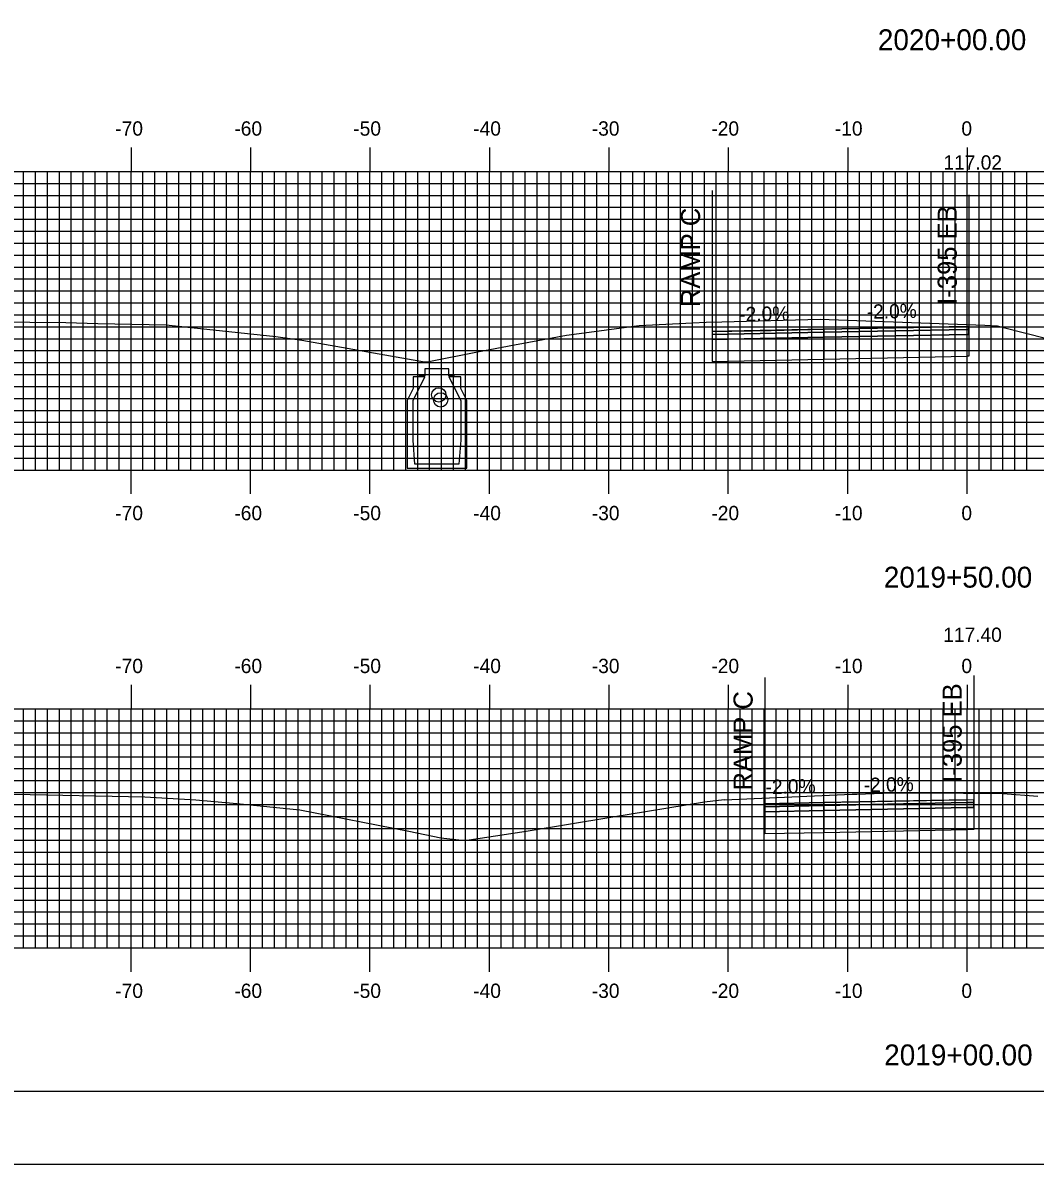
# Model space of a CAD drawing. Extents: x 855468 to 855811, y 366605 to 366825.
# Drawn here: x 855554.5 to 855639.3, y 366604.9 to 366700.5 of the extents above; entities that cross this region are included whole.
import ezdxf

# ---------------------------------------------------------------- set-up
doc = ezdxf.new("R2010")
doc.units = 0
for name, color, linetype in [('ANNOTATION', 7, 'Continuous'), ('BORDER', 7, 'Continuous'), ('D_Roadway_Centerline', 7, 'Continuous'), ('D_Roadway_Centerline_Text', 7, 'Continuous'), ('D_Roadway_Edge_Shoulder', 7, 'Continuous'), ('D_Roadway_Edge_TW', 7, 'Continuous'), ('D_Roadway_Pavement', 7, 'Continuous'), ('D_Roadway_SubGrade', 7, 'Continuous'), ('H_V ANNOTATION', 7, 'Continuous'), ('M_Roadway_Centerline', 7, 'Continuous'), ('MAJOR', 7, 'Continuous'), ('MINOR', 7, 'Continuous'), ('PLOT BOUNDARY', 7, 'Continuous'), ('S_Drainage_CB', 7, 'Continuous'), ('S_Drainage_Invert', 7, 'Continuous'), ('S_Roadway_Centerline', 7, 'Continuous')]:
    doc.layers.add(name, color=color, linetype=linetype)

msp = doc.modelspace()

# ---------------------------------------------------------------- linework, layer by layer
at = {"layer": 'BORDER'}
msp.add_lwpolyline([(855483.982, 366611.055), (855803.982, 366611.055), (855803.982, 366821.055), (855483.982, 366821.055)], close=True, dxfattribs=at)
at = {"layer": 'D_Roadway_Centerline'}
for points in [[(855612.235, 366674.653), (855612.237, 366674.653), (855617.18, 366674.752), (855621.581, 366674.84), (855621.582, 366674.84), (855633.579, 366675.08), (855633.583, 366675.08), (855633.63, 366675.081), (855633.729, 366675.083)], [(855616.641, 366635.117), (855621.581, 366635.216), (855621.583, 366635.216), (855633.065, 366635.446), (855633.583, 366635.456), (855633.602, 366635.457), (855634.141, 366635.467)]]:
    msp.add_lwpolyline(points, dxfattribs=at)
at = {"layer": 'D_Roadway_Edge_Shoulder'}
for points in [[(855633.582, 366675.08), (855633.729, 366675.083), (855633.729, 366674.833), (855633.582, 366674.83)], [(855633.583, 366635.456), (855634.141, 366635.467), (855634.141, 366635.217), (855633.583, 366635.206)]]:
    msp.add_lwpolyline(points, close=True, dxfattribs=at)
at = {"layer": 'D_Roadway_Edge_TW'}
for points in [[(855621.582, 366674.84), (855612.235, 366674.653), (855612.235, 366674.403), (855621.582, 366674.59)], [(855633.582, 366675.08), (855621.582, 366674.84), (855621.582, 366674.59), (855633.582, 366674.83)], [(855621.583, 366635.216), (855616.641, 366635.117), (855616.641, 366634.867), (855621.583, 366634.966)], [(855633.583, 366635.456), (855621.583, 366635.216), (855621.583, 366634.966), (855633.583, 366635.206)]]:
    msp.add_lwpolyline(points, close=True, dxfattribs=at)
for points in [[(855621.582, 366674.84), (855621.582, 366674.59)], [(855621.583, 366635.216), (855621.583, 366634.966)]]:
    msp.add_lwpolyline(points, dxfattribs=at)
at = {"layer": 'D_Roadway_Pavement'}
for points in [[(855621.582, 366674.59), (855612.235, 366674.403), (855612.235, 366673.987), (855621.582, 366674.173)], [(855633.582, 366674.83), (855621.582, 366674.59), (855621.582, 366674.173), (855633.582, 366674.413)], [(855633.582, 366674.83), (855633.729, 366674.833), (855633.729, 366674.416), (855633.582, 366674.413)], [(855633.583, 366635.206), (855621.583, 366634.966), (855621.583, 366634.549), (855633.583, 366634.789)], [(855633.583, 366635.206), (855634.141, 366635.217), (855634.141, 366634.801), (855633.583, 366634.789)], [(855621.583, 366634.966), (855616.641, 366634.867), (855616.641, 366634.451), (855621.583, 366634.549)]]:
    msp.add_lwpolyline(points, close=True, dxfattribs=at)
for points in [[(855621.582, 366674.59), (855621.582, 366674.173)], [(855621.582, 366674.59), (855621.582, 366674.173)], [(855621.583, 366634.966), (855621.583, 366634.549)], [(855621.583, 366634.966), (855621.583, 366634.549)]]:
    msp.add_lwpolyline(points, dxfattribs=at)
at = {"layer": 'D_Roadway_SubGrade'}
for p, q in [((855612.235, 366686.462), (855612.235, 366672.153)), ((855633.729, 366686.113), (855633.729, 366672.583)), ((855616.641, 366645.689), (855616.641, 366632.617)), ((855634.141, 366645.86), (855634.141, 366632.967))]:
    msp.add_line(p, q, dxfattribs=at)
for points in [[(855633.582, 366674.413), (855621.582, 366674.173), (855621.582, 366672.34), (855633.582, 366672.58)], [(855633.582, 366674.413), (855633.729, 366674.416), (855633.729, 366674.833), (855633.729, 366675.083), (855633.729, 366672.583), (855633.582, 366672.58)], [(855633.582, 366674.413), (855633.729, 366674.416), (855633.729, 366674.833), (855633.729, 366675.083), (855633.729, 366672.583), (855633.582, 366672.58)], [(855621.582, 366674.173), (855612.235, 366673.987), (855612.235, 366672.153), (855621.582, 366672.34)], [(855633.583, 366634.789), (855634.141, 366634.801), (855634.141, 366635.217), (855634.141, 366635.467), (855634.141, 366632.967), (855633.583, 366632.956)], [(855621.583, 366634.549), (855616.641, 366634.451), (855616.641, 366632.617), (855621.583, 366632.716)], [(855633.583, 366634.789), (855621.583, 366634.549), (855621.583, 366632.716), (855633.583, 366632.956)]]:
    msp.add_lwpolyline(points, close=True, dxfattribs=at)
for points in [[(855621.582, 366674.173), (855621.582, 366672.34)], [(855621.583, 366634.549), (855621.583, 366632.716)]]:
    msp.add_lwpolyline(points, dxfattribs=at)
at = {"layer": 'MAJOR'}
for p, q in [((855563.582, 366690.059), (855563.582, 366688.055)), ((855573.582, 366690.059), (855573.582, 366688.055)), ((855583.582, 366690.059), (855583.582, 366688.055)), ((855593.582, 366690.059), (855593.582, 366688.055)), ((855603.582, 366690.059), (855603.582, 366688.055)), ((855613.582, 366690.059), (855613.582, 366688.055)), ((855623.582, 366690.059), (855623.582, 366688.055)), ((855633.582, 366690.059), (855633.582, 366688.055)), ((855493.582, 366688.055), (855773.582, 366688.055)), ((855493.582, 366688.055), (855773.582, 366688.055)), ((855563.582, 366663.055), (855563.582, 366688.055)), ((855573.582, 366663.055), (855573.582, 366688.055)), ((855583.582, 366663.055), (855583.582, 366688.055)), ((855593.582, 366663.055), (855593.582, 366688.055)), ((855603.582, 366663.055), (855603.582, 366688.055)), ((855613.582, 366663.055), (855613.582, 366688.055)), ((855623.582, 366663.055), (855623.582, 366688.055)), ((855633.582, 366663.055), (855633.582, 366688.055)), ((855493.582, 366683.055), (855773.582, 366683.055)), ((855493.582, 366678.055), (855773.582, 366678.055)), ((855493.582, 366673.055), (855773.582, 366673.055)), ((855493.582, 366668.055), (855773.582, 366668.055)), ((855493.582, 366663.055), (855773.582, 366663.055)), ((855493.582, 366663.055), (855773.582, 366663.055)), ((855563.582, 366661.051), (855563.582, 366663.055)), ((855573.582, 366661.051), (855573.582, 366663.055)), ((855583.582, 366661.051), (855583.582, 366663.055)), ((855593.582, 366661.051), (855593.582, 366663.055)), ((855603.582, 366661.051), (855603.582, 366663.055)), ((855613.582, 366661.051), (855613.582, 366663.055)), ((855623.582, 366661.051), (855623.582, 366663.055)), ((855633.582, 366661.051), (855633.582, 366663.055)), ((855563.582, 366645.059), (855563.582, 366643.055)), ((855573.582, 366645.059), (855573.582, 366643.055)), ((855583.582, 366645.059), (855583.582, 366643.055)), ((855593.582, 366645.059), (855593.582, 366643.055)), ((855603.582, 366645.059), (855603.582, 366643.055)), ((855613.582, 366645.059), (855613.582, 366643.055)), ((855623.582, 366645.059), (855623.582, 366643.055)), ((855633.582, 366645.059), (855633.582, 366643.055)), ((855493.582, 366643.055), (855773.582, 366643.055)), ((855493.582, 366643.055), (855773.582, 366643.055)), ((855563.582, 366623.055), (855563.582, 366643.055)), ((855573.582, 366623.055), (855573.582, 366643.055)), ((855583.582, 366623.055), (855583.582, 366643.055)), ((855593.582, 366623.055), (855593.582, 366643.055)), ((855603.582, 366623.055), (855603.582, 366643.055)), ((855613.582, 366623.055), (855613.582, 366643.055)), ((855623.582, 366623.055), (855623.582, 366643.055)), ((855633.582, 366623.055), (855633.582, 366643.055)), ((855493.582, 366638.055), (855773.582, 366638.055)), ((855493.582, 366633.055), (855773.582, 366633.055)), ((855493.582, 366628.055), (855773.582, 366628.055)), ((855493.582, 366623.055), (855773.582, 366623.055)), ((855493.582, 366623.055), (855773.582, 366623.055)), ((855563.582, 366621.051), (855563.582, 366623.055)), ((855573.582, 366621.051), (855573.582, 366623.055)), ((855583.582, 366621.051), (855583.582, 366623.055)), ((855593.582, 366621.051), (855593.582, 366623.055)), ((855603.582, 366621.051), (855603.582, 366623.055)), ((855613.582, 366621.051), (855613.582, 366623.055)), ((855623.582, 366621.051), (855623.582, 366623.055)), ((855633.582, 366621.051), (855633.582, 366623.055))]:
    msp.add_line(p, q, dxfattribs=at)
at = {"layer": 'MINOR'}
for p, q in [((855554.582, 366663.055), (855554.582, 366688.055)), ((855555.582, 366663.055), (855555.582, 366688.055)), ((855556.582, 366663.055), (855556.582, 366688.055)), ((855557.582, 366663.055), (855557.582, 366688.055)), ((855558.582, 366663.055), (855558.582, 366688.055)), ((855559.582, 366663.055), (855559.582, 366688.055)), ((855560.582, 366663.055), (855560.582, 366688.055)), ((855561.582, 366663.055), (855561.582, 366688.055)), ((855562.582, 366663.055), (855562.582, 366688.055)), ((855564.582, 366663.055), (855564.582, 366688.055)), ((855565.582, 366663.055), (855565.582, 366688.055)), ((855566.582, 366663.055), (855566.582, 366688.055)), ((855567.582, 366663.055), (855567.582, 366688.055)), ((855568.582, 366663.055), (855568.582, 366688.055)), ((855569.582, 366663.055), (855569.582, 366688.055)), ((855570.582, 366663.055), (855570.582, 366688.055)), ((855571.582, 366663.055), (855571.582, 366688.055)), ((855572.582, 366663.055), (855572.582, 366688.055)), ((855574.582, 366663.055), (855574.582, 366688.055)), ((855575.582, 366663.055), (855575.582, 366688.055)), ((855576.582, 366663.055), (855576.582, 366688.055)), ((855577.582, 366663.055), (855577.582, 366688.055)), ((855578.582, 366663.055), (855578.582, 366688.055)), ((855579.582, 366663.055), (855579.582, 366688.055)), ((855580.582, 366663.055), (855580.582, 366688.055)), ((855581.582, 366663.055), (855581.582, 366688.055)), ((855582.582, 366663.055), (855582.582, 366688.055)), ((855584.582, 366663.055), (855584.582, 366688.055)), ((855585.582, 366663.055), (855585.582, 366688.055)), ((855586.582, 366663.055), (855586.582, 366688.055)), ((855587.582, 366663.055), (855587.582, 366688.055)), ((855588.582, 366663.055), (855588.582, 366688.055)), ((855589.582, 366663.055), (855589.582, 366688.055)), ((855590.582, 366663.055), (855590.582, 366688.055)), ((855591.582, 366663.055), (855591.582, 366688.055)), ((855592.582, 366663.055), (855592.582, 366688.055)), ((855594.582, 366663.055), (855594.582, 366688.055)), ((855595.582, 366663.055), (855595.582, 366688.055)), ((855596.582, 366663.055), (855596.582, 366688.055)), ((855597.582, 366663.055), (855597.582, 366688.055)), ((855598.582, 366663.055), (855598.582, 366688.055)), ((855599.582, 366663.055), (855599.582, 366688.055)), ((855600.582, 366663.055), (855600.582, 366688.055)), ((855601.582, 366663.055), (855601.582, 366688.055)), ((855602.582, 366663.055), (855602.582, 366688.055)), ((855604.582, 366663.055), (855604.582, 366688.055)), ((855605.582, 366663.055), (855605.582, 366688.055)), ((855606.582, 366663.055), (855606.582, 366688.055)), ((855607.582, 366663.055), (855607.582, 366688.055)), ((855608.582, 366663.055), (855608.582, 366688.055)), ((855609.582, 366663.055), (855609.582, 366688.055)), ((855610.582, 366663.055), (855610.582, 366688.055)), ((855611.582, 366663.055), (855611.582, 366688.055)), ((855612.582, 366663.055), (855612.582, 366688.055)), ((855614.582, 366663.055), (855614.582, 366688.055)), ((855615.582, 366663.055), (855615.582, 366688.055)), ((855616.582, 366663.055), (855616.582, 366688.055)), ((855617.582, 366663.055), (855617.582, 366688.055)), ((855618.582, 366663.055), (855618.582, 366688.055)), ((855619.582, 366663.055), (855619.582, 366688.055)), ((855620.582, 366663.055), (855620.582, 366688.055)), ((855621.582, 366663.055), (855621.582, 366688.055)), ((855622.582, 366663.055), (855622.582, 366688.055)), ((855624.582, 366663.055), (855624.582, 366688.055)), ((855625.582, 366663.055), (855625.582, 366688.055)), ((855626.582, 366663.055), (855626.582, 366688.055)), ((855627.582, 366663.055), (855627.582, 366688.055)), ((855628.582, 366663.055), (855628.582, 366688.055)), ((855629.582, 366663.055), (855629.582, 366688.055)), ((855630.582, 366663.055), (855630.582, 366688.055)), ((855631.582, 366663.055), (855631.582, 366688.055)), ((855632.582, 366663.055), (855632.582, 366688.055)), ((855634.582, 366663.055), (855634.582, 366688.055)), ((855635.582, 366663.055), (855635.582, 366688.055)), ((855636.582, 366663.055), (855636.582, 366688.055)), ((855637.582, 366663.055), (855637.582, 366688.055)), ((855638.582, 366663.055), (855638.582, 366688.055)), ((855493.582, 366687.055), (855773.582, 366687.055)), ((855493.582, 366686.055), (855773.582, 366686.055)), ((855493.582, 366685.055), (855773.582, 366685.055)), ((855493.582, 366684.055), (855773.582, 366684.055)), ((855493.582, 366682.055), (855773.582, 366682.055)), ((855493.582, 366681.055), (855773.582, 366681.055)), ((855493.582, 366680.055), (855773.582, 366680.055)), ((855493.582, 366679.055), (855773.582, 366679.055)), ((855493.582, 366677.055), (855773.582, 366677.055)), ((855493.582, 366676.055), (855773.582, 366676.055)), ((855493.582, 366675.055), (855773.582, 366675.055)), ((855493.582, 366674.055), (855773.582, 366674.055)), ((855493.582, 366672.055), (855773.582, 366672.055)), ((855493.582, 366671.055), (855773.582, 366671.055)), ((855493.582, 366670.055), (855773.582, 366670.055)), ((855493.582, 366669.055), (855773.582, 366669.055)), ((855493.582, 366667.055), (855773.582, 366667.055)), ((855493.582, 366666.055), (855773.582, 366666.055)), ((855493.582, 366665.055), (855773.582, 366665.055)), ((855493.582, 366664.055), (855773.582, 366664.055)), ((855554.582, 366623.055), (855554.582, 366643.055)), ((855555.582, 366623.055), (855555.582, 366643.055)), ((855556.582, 366623.055), (855556.582, 366643.055)), ((855557.582, 366623.055), (855557.582, 366643.055)), ((855558.582, 366623.055), (855558.582, 366643.055)), ((855559.582, 366623.055), (855559.582, 366643.055)), ((855560.582, 366623.055), (855560.582, 366643.055)), ((855561.582, 366623.055), (855561.582, 366643.055)), ((855562.582, 366623.055), (855562.582, 366643.055)), ((855564.582, 366623.055), (855564.582, 366643.055)), ((855565.582, 366623.055), (855565.582, 366643.055)), ((855566.582, 366623.055), (855566.582, 366643.055)), ((855567.582, 366623.055), (855567.582, 366643.055)), ((855568.582, 366623.055), (855568.582, 366643.055)), ((855569.582, 366623.055), (855569.582, 366643.055)), ((855570.582, 366623.055), (855570.582, 366643.055)), ((855571.582, 366623.055), (855571.582, 366643.055)), ((855572.582, 366623.055), (855572.582, 366643.055)), ((855574.582, 366623.055), (855574.582, 366643.055)), ((855575.582, 366623.055), (855575.582, 366643.055)), ((855576.582, 366623.055), (855576.582, 366643.055)), ((855577.582, 366623.055), (855577.582, 366643.055)), ((855578.582, 366623.055), (855578.582, 366643.055)), ((855579.582, 366623.055), (855579.582, 366643.055)), ((855580.582, 366623.055), (855580.582, 366643.055)), ((855581.582, 366623.055), (855581.582, 366643.055)), ((855582.582, 366623.055), (855582.582, 366643.055)), ((855584.582, 366623.055), (855584.582, 366643.055)), ((855585.582, 366623.055), (855585.582, 366643.055)), ((855586.582, 366623.055), (855586.582, 366643.055)), ((855587.582, 366623.055), (855587.582, 366643.055)), ((855588.582, 366623.055), (855588.582, 366643.055)), ((855589.582, 366623.055), (855589.582, 366643.055)), ((855590.582, 366623.055), (855590.582, 366643.055)), ((855591.582, 366623.055), (855591.582, 366643.055)), ((855592.582, 366623.055), (855592.582, 366643.055)), ((855594.582, 366623.055), (855594.582, 366643.055)), ((855595.582, 366623.055), (855595.582, 366643.055)), ((855596.582, 366623.055), (855596.582, 366643.055)), ((855597.582, 366623.055), (855597.582, 366643.055)), ((855598.582, 366623.055), (855598.582, 366643.055)), ((855599.582, 366623.055), (855599.582, 366643.055)), ((855600.582, 366623.055), (855600.582, 366643.055)), ((855601.582, 366623.055), (855601.582, 366643.055)), ((855602.582, 366623.055), (855602.582, 366643.055)), ((855604.582, 366623.055), (855604.582, 366643.055)), ((855605.582, 366623.055), (855605.582, 366643.055)), ((855606.582, 366623.055), (855606.582, 366643.055)), ((855607.582, 366623.055), (855607.582, 366643.055)), ((855608.582, 366623.055), (855608.582, 366643.055)), ((855609.582, 366623.055), (855609.582, 366643.055)), ((855610.582, 366623.055), (855610.582, 366643.055)), ((855611.582, 366623.055), (855611.582, 366643.055)), ((855612.582, 366623.055), (855612.582, 366643.055)), ((855614.582, 366623.055), (855614.582, 366643.055)), ((855615.582, 366623.055), (855615.582, 366643.055)), ((855616.582, 366623.055), (855616.582, 366643.055)), ((855617.582, 366623.055), (855617.582, 366643.055)), ((855618.582, 366623.055), (855618.582, 366643.055)), ((855619.582, 366623.055), (855619.582, 366643.055)), ((855620.582, 366623.055), (855620.582, 366643.055)), ((855621.582, 366623.055), (855621.582, 366643.055)), ((855622.582, 366623.055), (855622.582, 366643.055)), ((855624.582, 366623.055), (855624.582, 366643.055)), ((855625.582, 366623.055), (855625.582, 366643.055)), ((855626.582, 366623.055), (855626.582, 366643.055)), ((855627.582, 366623.055), (855627.582, 366643.055)), ((855628.582, 366623.055), (855628.582, 366643.055)), ((855629.582, 366623.055), (855629.582, 366643.055)), ((855630.582, 366623.055), (855630.582, 366643.055)), ((855631.582, 366623.055), (855631.582, 366643.055)), ((855632.582, 366623.055), (855632.582, 366643.055)), ((855634.582, 366623.055), (855634.582, 366643.055)), ((855635.582, 366623.055), (855635.582, 366643.055)), ((855636.582, 366623.055), (855636.582, 366643.055)), ((855637.582, 366623.055), (855637.582, 366643.055)), ((855638.582, 366623.055), (855638.582, 366643.055)), ((855493.582, 366642.055), (855773.582, 366642.055)), ((855493.582, 366641.055), (855773.582, 366641.055)), ((855493.582, 366640.055), (855773.582, 366640.055)), ((855493.582, 366639.055), (855773.582, 366639.055)), ((855493.582, 366637.055), (855773.582, 366637.055)), ((855493.582, 366636.055), (855773.582, 366636.055)), ((855493.582, 366635.055), (855773.582, 366635.055)), ((855493.582, 366634.055), (855773.582, 366634.055)), ((855493.582, 366632.055), (855773.582, 366632.055)), ((855493.582, 366631.055), (855773.582, 366631.055)), ((855493.582, 366630.055), (855773.582, 366630.055)), ((855493.582, 366629.055), (855773.582, 366629.055)), ((855493.582, 366627.055), (855773.582, 366627.055)), ((855493.582, 366626.055), (855773.582, 366626.055)), ((855493.582, 366625.055), (855773.582, 366625.055)), ((855493.582, 366624.055), (855773.582, 366624.055))]:
    msp.add_line(p, q, dxfattribs=at)
at = {"layer": 'PLOT BOUNDARY'}
msp.add_lwpolyline([(855467.796, 366604.937), (855807.796, 366604.937), (855807.796, 366824.937), (855467.796, 366824.937)], close=True, dxfattribs=at)
at = {"layer": 'S_Drainage_CB'}
for p, q in [((855588.177, 366670.869), (855587.193, 366670.869)), ((855587.193, 366670.869), (855587.193, 366669.885)), ((855587.193, 366668.867), (855588.177, 366670.869)), ((855591.196, 366670.869), (855590.179, 366670.869)), ((855590.179, 366670.869), (855591.196, 366668.867)), ((855591.196, 366669.885), (855591.196, 366670.869)), ((855587.193, 366669.885), (855586.701, 366668.867)), ((855591.688, 366668.867), (855591.196, 366669.885)), ((855586.701, 366668.867), (855586.701, 366663.224)), ((855587.193, 366665.554), (855587.193, 366668.867)), ((855591.196, 366668.867), (855591.196, 366665.554)), ((855591.688, 366663.224), (855591.688, 366668.867)), ((855587.357, 366663.553), (855587.193, 366665.554)), ((855591.196, 366665.554), (855591.032, 366663.553)), ((855586.701, 366663.224), (855591.688, 366663.224)), ((855591.032, 366663.553), (855587.357, 366663.553))]:
    msp.add_line(p, q, dxfattribs=at)
msp.add_lwpolyline([(855590.671, 366670.91), (855590.179, 366670.91), (855590.179, 366671.534), (855588.177, 366671.534), (855588.177, 366670.91), (855587.685, 366670.91)], dxfattribs=at)
at = {"layer": 'S_Drainage_Invert'}
for centre in [(855589.346, 366669.353), (855589.509, 366668.933)]:
    msp.add_circle(centre, 0.6, dxfattribs=at)
at = {"layer": 'S_Roadway_Centerline'}
for points in [[(855550.769, 366675.493), (855555.125, 366675.447), (855558.133, 366675.406), (855560.803, 366675.329), (855566.539, 366675.217), (855566.767, 366675.174), (855575.697, 366674.226), (855577.892, 366673.94), (855588.141, 366672.128), (855588.372, 366672.122), (855592.586, 366672.952), (855595.694, 366673.554), (855600.04, 366674.344), (855606.12, 366675.154), (855610.578, 366675.374), (855611.727, 366675.435), (855613.046, 366675.476), (855619.21, 366675.638), (855621.289, 366675.697), (855635.067, 366675.177), (855636.008, 366675.138), (855636.087, 366675.133), (855636.517, 366675.015), (855640.247, 366674.072)], [(855553.765, 366635.91), (855564.742, 366635.682), (855565.689, 366635.652), (855568.998, 366635.456), (855572.442, 366635.137), (855577.729, 366634.6), (855586.854, 366632.814), (855589.534, 366632.269), (855591.521, 366632.034), (855596.676, 366632.822), (855603.757, 366634.003), (855611.586, 366635.267), (855613.245, 366635.464), (855613.255, 366635.44), (855623.954, 366635.915), (855624.354, 366635.931), (855626.529, 366635.994), (855629.998, 366636.019), (855636.565, 366635.966), (855639.506, 366635.754)]]:
    msp.add_lwpolyline(points, dxfattribs=at)

# ---------------------------------------------------------------- texts
at = {"layer": 'ANNOTATION'}
for s, height, rotation, p in [('RAMP C', 1.6, 90, (855611.222, 366676.698)), ('I-395 EB', 1.6, 90, (855632.715, 366676.895)), ('-2.0%', 1.2, 1.14618, (855614.515, 366675.499)), ('-2.0%', 1.2, 1.14574, (855625.187, 366675.713)), ('I-395 EB', 1.6, 90, (855633.127, 366636.874)), ('RAMP C', 1.6, 90, (855615.627, 366636.225)), ('-2.0%', 1.2, 1.14778, (855616.717, 366635.919)), ('-2.0%', 1.2, 1.14573, (855624.93, 366636.084))]:
    msp.add_text(s, height=height, rotation=rotation, dxfattribs=at).set_placement(p)
at = {"layer": 'D_Roadway_Centerline_Text'}
for s, p in [('117.02', (855631.595, 366688.209)), ('117.40', (855631.579, 366648.664))]:
    msp.add_text(s, height=1.2, dxfattribs=at).set_placement(p)
at = {"layer": 'H_V ANNOTATION'}
for s, height, p in [('2020+00.00', 1.75, (855626.107, 366698.211)), ('-70', 1.2, (855562.266, 366691.055)), ('-60', 1.2, (855572.234, 366691.055)), ('-50', 1.2, (855582.191, 366691.055)), ('-40', 1.2, (855592.234, 366691.055)), ('-30', 1.2, (855602.159, 366691.055)), ('-20', 1.2, (855612.169, 366691.055)), ('-10', 1.2, (855622.512, 366691.055)), ('0', 1.2, (855633.101, 366691.055)), ('-70', 1.2, (855562.266, 366658.855)), ('-60', 1.2, (855572.234, 366658.855)), ('-50', 1.2, (855582.191, 366658.855)), ('-40', 1.2, (855592.234, 366658.855)), ('-30', 1.2, (855602.159, 366658.855)), ('-20', 1.2, (855612.169, 366658.855)), ('-10', 1.2, (855622.512, 366658.855)), ('0', 1.2, (855633.101, 366658.855)), ('2019+50.00', 1.75, (855626.606, 366653.211)), ('-70', 1.2, (855562.266, 366646.055)), ('-60', 1.2, (855572.234, 366646.055)), ('-50', 1.2, (855582.191, 366646.055)), ('-40', 1.2, (855592.234, 366646.055)), ('-30', 1.2, (855602.159, 366646.055)), ('-20', 1.2, (855612.169, 366646.055)), ('-10', 1.2, (855622.512, 366646.055)), ('0', 1.2, (855633.101, 366646.055)), ('-70', 1.2, (855562.266, 366618.855)), ('-60', 1.2, (855572.234, 366618.855)), ('-50', 1.2, (855582.191, 366618.855)), ('-40', 1.2, (855592.234, 366618.855)), ('-30', 1.2, (855602.159, 366618.855)), ('-20', 1.2, (855612.169, 366618.855)), ('-10', 1.2, (855622.512, 366618.855)), ('0', 1.2, (855633.101, 366618.855)), ('2019+00.00', 1.75, (855626.638, 366613.211))]:
    msp.add_text(s, height=height, dxfattribs=at).set_placement(p)
at = {"layer": 'M_Roadway_Centerline'}
for s, p in [('C', (855619.204, 366675.638)), ('L', (855619.21, 366675.631)), ('C', (855626.524, 366635.994)), ('L', (855626.529, 366635.987))]:
    msp.add_text(s, height=0.0146, dxfattribs=at).set_placement(p)

doc.saveas('drawing.dxf')
